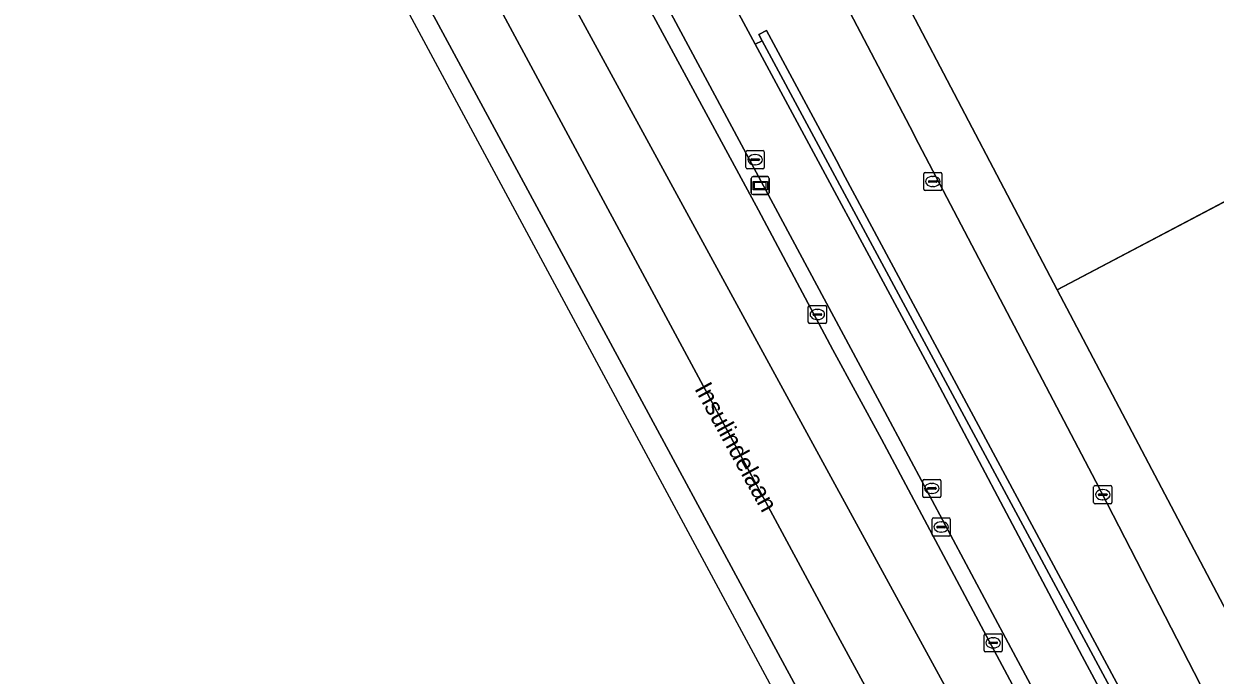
# Model space of a CAD drawing. Extents: x 162879 to 165540, y 384011 to 385181.
# Drawn here: x 162913.3 to 162979.1, y 384082.2 to 384118.2 of the extents above; entities that cross this region are included whole.
import ezdxf

# ---------------------------------------------------------------- set-up
doc = ezdxf.new("R2010")
doc.units = 0
for name, color, linetype in [('IMGEO_Berm_groen', 7, 'Continuous'), ('IMGEO_Berm_open', 7, 'Continuous'), ('IMGEO_Erf', 7, 'Continuous'), ('IMGEO_Fietspad_open', 7, 'Continuous'), ('IMGEO_Groenvoorziening', 7, 'Continuous'), ('IMGEO_Hek', 7, 'Continuous'), ('IMGEO_Kolk', 7, 'Continuous'), ('IMGEO_Muur', 7, 'Continuous'), ('IMGEO_Openbare_ruimte_label', 7, 'Continuous'), ('IMGEO_Rijbaan_regionaal_gesloten', 7, 'Continuous'), ('IMGEO_Rioolput', 7, 'Continuous'), ('IMGEO_Voetpad_open', 7, 'Continuous'), ('IMGEO_Wegwijzer', 7, 'Continuous')]:
    doc.layers.add(name, color=color, linetype=linetype)

msp = doc.modelspace()

# ---------------------------------------------------------------- linework, layer by layer
at = {"layer": 'IMGEO_Berm_groen'}
msp.add_lwpolyline([(162933.038, 384155.899), (162937.872, 384146.488), (162947.223, 384129.106), (162953.721, 384117.028), (162954.108, 384117.22), (162953.92, 384117.569), (162954.341, 384117.797), (162958.202, 384110.605), (162958.691, 384109.694), (162981.431, 384067.333), (162984.67, 384069.309), (162972.528, 384092.889), (162962.739, 384111.555), (162962.245, 384112.496), (162934.711, 384164.997)], dxfattribs=at)
at = {"layer": 'IMGEO_Berm_open'}
for points in [[(162930.309, 384154.083), (162929.465, 384153.664), (162929.808, 384152.971), (162933.346, 384146.147), (162936.921, 384139.438), (162942.396, 384129.219), (162947.989, 384118.779), (162953.892, 384107.862), (162957.998, 384100.168), (162960.687, 384095.222), (162966.347, 384084.631), (162969.056, 384079.527), (162972.201, 384073.655), (162975.924, 384066.775), (162977.549, 384063.861)], [(162978.275, 384064.218), (162977.652, 384065.394), (162972.657, 384074.738), (162967.836, 384083.704), (162960.872, 384096.737), (162947.738, 384121.235), (162934.999, 384144.935), (162933.549, 384147.714), (162932.265, 384150.139), (162930.309, 384154.083)]]:
    msp.add_lwpolyline(points, dxfattribs=at)
at = {"layer": 'IMGEO_Erf'}
msp.add_lwpolyline([(163003.813, 384097.747), (163004.613, 384098.171), (162997.371, 384111.834), (162989.485, 384113.534), (162970.391, 384103.478), (162987.483, 384071.025), (162995.091, 384074.97), (163000, 384077.515), (163012.207, 384083.845), (163007.504, 384092.716), (163006.694, 384092.288), (163005.778, 384094.016), (163003.752, 384092.942), (163002.029, 384096.192), (163004.066, 384097.271)], close=True, dxfattribs=at)
at = {"layer": 'IMGEO_Fietspad_open'}
for points in [[(162953.721, 384117.028), (162947.223, 384129.106), (162937.872, 384146.488), (162933.038, 384155.899)], [(162930.309, 384154.083), (162932.265, 384150.139), (162933.549, 384147.714), (162934.999, 384144.935), (162947.738, 384121.235), (162960.872, 384096.737), (162967.836, 384083.704), (162972.657, 384074.738), (162977.652, 384065.394), (162978.275, 384064.218)], [(162980.802, 384066.421), (162971.761, 384083.25), (162963.737, 384098.409), (162953.721, 384117.028)]]:
    msp.add_lwpolyline(points, dxfattribs=at)
at = {"layer": 'IMGEO_Groenvoorziening'}
msp.add_lwpolyline([(162962.154, 384119.148), (162970.391, 384103.478), (162989.485, 384113.534), (162997.371, 384111.834), (163004.613, 384098.171), (163007.401, 384092.911), (163010.958, 384094.796), (163011.072, 384094.58), (163015.763, 384085.73), (163017.147, 384083.12), (163017.364, 384083.229), (163017.549, 384082.865), (163022.409, 384085.444), (163024.815, 384086.721), (163049.609, 384099.879)], dxfattribs=at)
at = {"layer": 'IMGEO_Hek'}
msp.add_lwpolyline([(162970.391, 384103.478), (162987.968, 384112.735)], dxfattribs=at)
at = {"layer": 'IMGEO_Kolk'}
for p, q in [((162953.285, 384111.158), (162954.137, 384111.158)), ((162953.21, 384110.232), (162953.21, 384111.084)), ((162953.469, 384110.652), (162953.469, 384110.664)), ((162953.907, 384110.615), (162953.509, 384110.615)), ((162953.512, 384110.701), (162953.91, 384110.701)), ((162953.698, 384110.938), (162953.723, 384110.938)), ((162953.953, 384110.664), (162953.953, 384110.652)), ((162954.211, 384111.084), (162954.211, 384110.232)), ((162954.137, 384110.158), (162953.285, 384110.158)), ((162953.721, 384110.378), (162953.696, 384110.378)), ((162956.722, 384102.614), (162957.574, 384102.614)), ((162956.647, 384101.688), (162956.647, 384102.54)), ((162956.906, 384102.108), (162956.906, 384102.12)), ((162957.344, 384102.071), (162956.946, 384102.071)), ((162956.949, 384102.157), (162957.347, 384102.157)), ((162957.135, 384102.394), (162957.16, 384102.394)), ((162957.39, 384102.12), (162957.39, 384102.108)), ((162957.648, 384102.54), (162957.648, 384101.688)), ((162957.574, 384101.614), (162956.722, 384101.614)), ((162957.158, 384101.834), (162957.133, 384101.834)), ((162962.967, 384092.085), (162962.967, 384092.937)), ((162963.042, 384093.011), (162963.894, 384093.011)), ((162963.455, 384092.791), (162963.48, 384092.791)), ((162963.968, 384092.937), (162963.968, 384092.085)), ((162963.226, 384092.505), (162963.226, 384092.517)), ((162963.664, 384092.468), (162963.266, 384092.468)), ((162963.269, 384092.554), (162963.667, 384092.554)), ((162963.478, 384092.231), (162963.453, 384092.231)), ((162963.71, 384092.517), (162963.71, 384092.505)), ((162972.401, 384091.738), (162972.401, 384092.59)), ((162972.476, 384092.664), (162973.328, 384092.664)), ((162972.66, 384092.158), (162972.66, 384092.17)), ((162973.098, 384092.121), (162972.7, 384092.121)), ((162972.703, 384092.207), (162973.101, 384092.207)), ((162972.889, 384092.444), (162972.914, 384092.444)), ((162973.144, 384092.17), (162973.144, 384092.158)), ((162973.402, 384092.59), (162973.402, 384091.738)), ((162963.894, 384092.011), (162963.042, 384092.011)), ((162973.328, 384091.664), (162972.476, 384091.664)), ((162972.912, 384091.884), (162972.887, 384091.884)), ((162966.354, 384083.558), (162966.354, 384084.41)), ((162966.429, 384084.484), (162967.281, 384084.484)), ((162966.842, 384084.264), (162966.867, 384084.264)), ((162967.355, 384084.41), (162967.355, 384083.558)), ((162967.281, 384083.484), (162966.429, 384083.484)), ((162966.613, 384083.978), (162966.613, 384083.99)), ((162967.051, 384083.941), (162966.653, 384083.941)), ((162966.656, 384084.027), (162967.054, 384084.027)), ((162966.865, 384083.704), (162966.84, 384083.704)), ((162967.097, 384083.99), (162967.097, 384083.978))]:
    msp.add_line(p, q, dxfattribs=at)
for points in [[(162953.285, 384111.158), (162954.137, 384111.158)], [(162953.21, 384110.232), (162953.21, 384111.084)], [(162954.211, 384111.084), (162954.211, 384110.232)], [(162954.137, 384110.158), (162953.285, 384110.158)], [(162956.722, 384102.614), (162957.574, 384102.614)], [(162956.647, 384101.688), (162956.647, 384102.54)], [(162957.648, 384102.54), (162957.648, 384101.688)], [(162957.574, 384101.614), (162956.722, 384101.614)], [(162962.967, 384092.085), (162962.967, 384092.937)], [(162963.042, 384093.011), (162963.894, 384093.011)], [(162963.968, 384092.937), (162963.968, 384092.085)], [(162972.401, 384091.738), (162972.401, 384092.59)], [(162972.476, 384092.664), (162973.328, 384092.664)], [(162973.402, 384092.59), (162973.402, 384091.738)], [(162963.894, 384092.011), (162963.042, 384092.011)], [(162973.328, 384091.664), (162972.476, 384091.664)], [(162966.354, 384083.558), (162966.354, 384084.41)], [(162966.429, 384084.484), (162967.281, 384084.484)], [(162967.355, 384084.41), (162967.355, 384083.558)], [(162967.281, 384083.484), (162966.429, 384083.484)]]:
    msp.add_lwpolyline(points, dxfattribs=at)
for centre, radius, start, end in [((162953.287, 384111.082), 0.0765, 91.55205, 178.44795), ((162953.287, 384111.082), 0.0765, 91.55205, 178.44795), ((162954.135, 384111.082), 0.0765, 1.55205, 88.44795), ((162954.135, 384111.082), 0.0765, 1.55205, 88.44795), ((162953.509, 384110.661), 0.0403, 85.87752, 175.75265), ((162953.506, 384110.651), 0.0366, 178.93798, 274.71019), ((162953.91, 384110.658), 0.043, 264.86636, 352.45326), ((162953.914, 384110.663), 0.0386, 1.73085, 96.63898), ((162953.287, 384110.234), 0.0765, 181.55205, 268.44795), ((162953.287, 384110.234), 0.0765, 181.55205, 268.44795), ((162954.135, 384110.234), 0.0765, 271.55205, 358.44795), ((162954.135, 384110.234), 0.0765, 271.55205, 358.44795), ((162956.724, 384102.538), 0.0765, 91.55205, 178.44795), ((162956.724, 384102.538), 0.0765, 91.55205, 178.44795), ((162957.572, 384102.538), 0.0765, 1.55205, 88.44795), ((162957.572, 384102.538), 0.0765, 1.55205, 88.44795), ((162956.946, 384102.117), 0.0403, 85.87752, 175.75265), ((162956.943, 384102.107), 0.0366, 178.93798, 274.71019), ((162957.347, 384102.114), 0.043, 264.86636, 352.45326), ((162957.351, 384102.119), 0.0386, 1.73085, 96.63898), ((162956.724, 384101.69), 0.0765, 181.55205, 268.44795), ((162956.724, 384101.69), 0.0765, 181.55205, 268.44795), ((162957.572, 384101.69), 0.0765, 271.55205, 358.44795), ((162957.572, 384101.69), 0.0765, 271.55205, 358.44795), ((162963.044, 384092.935), 0.0765, 91.55205, 178.44795), ((162963.044, 384092.935), 0.0765, 91.55205, 178.44795), ((162963.892, 384092.935), 0.0765, 1.55205, 88.44795), ((162963.892, 384092.935), 0.0765, 1.55205, 88.44795), ((162963.044, 384092.087), 0.0765, 181.55205, 268.44795), ((162963.044, 384092.087), 0.0765, 181.55205, 268.44795), ((162963.266, 384092.514), 0.0403, 85.87752, 175.75265), ((162963.263, 384092.504), 0.0366, 178.93798, 274.71019), ((162963.667, 384092.511), 0.043, 264.86636, 352.45326), ((162963.671, 384092.516), 0.0386, 1.73085, 96.63898), ((162963.892, 384092.087), 0.0765, 271.55205, 358.44795), ((162963.892, 384092.087), 0.0765, 271.55205, 358.44795), ((162972.478, 384092.588), 0.0765, 91.55205, 178.44795), ((162972.478, 384092.588), 0.0765, 91.55205, 178.44795), ((162972.7, 384092.167), 0.0403, 85.87752, 175.75265), ((162972.697, 384092.157), 0.0366, 178.93798, 274.71019), ((162973.101, 384092.164), 0.043, 264.86636, 352.45326), ((162973.105, 384092.169), 0.0386, 1.73085, 96.63898), ((162973.326, 384092.588), 0.0765, 1.55205, 88.44795), ((162973.326, 384092.588), 0.0765, 1.55205, 88.44795), ((162972.478, 384091.74), 0.0765, 181.55205, 268.44795), ((162972.478, 384091.74), 0.0765, 181.55205, 268.44795), ((162973.326, 384091.74), 0.0765, 271.55205, 358.44795), ((162973.326, 384091.74), 0.0765, 271.55205, 358.44795), ((162966.431, 384084.408), 0.0765, 91.55205, 178.44795), ((162966.431, 384084.408), 0.0765, 91.55205, 178.44795), ((162967.279, 384084.408), 0.0765, 1.55205, 88.44795), ((162967.279, 384084.408), 0.0765, 1.55205, 88.44795), ((162966.431, 384083.56), 0.0765, 181.55205, 268.44795), ((162966.431, 384083.56), 0.0765, 181.55205, 268.44795), ((162966.653, 384083.987), 0.0403, 85.87752, 175.75265), ((162966.65, 384083.977), 0.0366, 178.93798, 274.71019), ((162967.054, 384083.984), 0.043, 264.86636, 352.45326), ((162967.058, 384083.989), 0.0386, 1.73085, 96.63898), ((162967.279, 384083.56), 0.0765, 271.55205, 358.44795), ((162967.279, 384083.56), 0.0765, 271.55205, 358.44795)]:
    msp.add_arc(centre, radius, start, end, dxfattribs=at)
for centre, major_axis, ratio, start_param, end_param in [((162953.697, 384110.658), (-0.387, 0.002), 0.722429, 4.712389, 7.853982), ((162953.722, 384110.658), (-0.39, 0.002), 0.717154, 1.570796, 4.712389), ((162957.134, 384102.114), (-0.387, 0.002), 0.722429, 4.712389, 7.853982), ((162957.159, 384102.114), (-0.39, 0.002), 0.717154, 1.570796, 4.712389), ((162963.454, 384092.511), (-0.387, 0.002), 0.722429, 4.712389, 7.853982), ((162963.479, 384092.511), (-0.39, 0.002), 0.717154, 1.570796, 4.712389), ((162972.888, 384092.164), (-0.387, 0.002), 0.722429, 4.712389, 7.853982), ((162972.913, 384092.164), (-0.39, 0.002), 0.717154, 1.570796, 4.712389), ((162966.841, 384083.984), (-0.387, 0.002), 0.722429, 4.712389, 7.853982), ((162966.866, 384083.984), (-0.39, 0.002), 0.717154, 1.570796, 4.712389)]:
    msp.add_ellipse(centre, major_axis=major_axis, ratio=ratio, start_param=start_param, end_param=end_param, dxfattribs=at)
at = {"layer": 'IMGEO_Muur'}
msp.add_lwpolyline([(162954.341, 384117.797), (162953.92, 384117.569), (162954.108, 384117.22), (162990.798, 384049.049), (162991.582, 384049.441), (163000.702, 384054.002), (163002.277, 384054.79), (163002.133, 384055.152), (163000.563, 384054.317), (162991.01, 384049.488), (162981.431, 384067.333), (162958.691, 384109.694), (162958.202, 384110.605)], close=True, dxfattribs=at)
at = {"layer": 'IMGEO_Rijbaan_regionaal_gesloten'}
for points in [[(162973.315, 384058.937), (162975.292, 384061.236), (162941.468, 384123.295), (162927.054, 384149.995), (162925.32, 384153.606), (162923.876, 384157.224), (162922.622, 384160.668), (162921.527, 384164.257), (162920.544, 384168.175), (162919.842, 384172.079), (162919.29, 384176.002), (162918.834, 384180.023), (162918.728, 384184.033), (162918.781, 384187.947), (162919.067, 384191.957), (162919.5, 384195.956)], [(162972.6, 384059.067), (162968.149, 384066.24), (162958.401, 384084.137), (162938.264, 384121.566), (162923.818, 384148.334), (162921.12, 384153.691), (162919.483, 384157.241), (162917.376, 384162.869), (162917.1, 384164.017), (162916.031, 384170.737)], [(162916.031, 384170.737), (162917.1, 384164.017), (162917.376, 384162.869), (162919.483, 384157.241), (162921.12, 384153.691), (162923.818, 384148.334), (162938.264, 384121.566), (162958.401, 384084.137), (162968.149, 384066.24), (162972.6, 384059.067)], [(162913.346, 384158.234), (162988.206, 384019.169)], [(162953.892, 384107.862), (162947.989, 384118.779), (162942.396, 384129.219), (162936.921, 384139.438), (162933.346, 384146.147), (162929.808, 384152.971), (162929.465, 384153.664)], [(162941.468, 384123.295), (162975.292, 384061.236), (162977.549, 384063.861), (162975.924, 384066.775), (162972.201, 384073.655), (162969.056, 384079.527), (162966.347, 384084.631), (162960.687, 384095.222), (162957.998, 384100.168), (162953.892, 384107.862)], [(162934.139, 384122.004), (162969.546, 384056.451), (162985.285, 384027.338), (162989.779, 384019.039), (162993.944, 384018.694), (162977.19, 384049.734), (162972.482, 384058.455)], [(162988.206, 384019.169), (162989.779, 384019.039), (162985.285, 384027.338), (162969.546, 384056.451), (162934.139, 384122.004)]]:
    msp.add_lwpolyline(points, dxfattribs=at)
at = {"layer": 'IMGEO_Rioolput'}
for p, q in [((162963.022, 384109.028), (162963.022, 384109.88)), ((162963.097, 384109.954), (162963.949, 384109.954)), ((162964.023, 384109.88), (162964.023, 384109.028)), ((162963.281, 384109.448), (162963.281, 384109.46)), ((162963.719, 384109.411), (162963.321, 384109.411)), ((162963.324, 384109.497), (162963.722, 384109.497)), ((162963.533, 384109.174), (162963.508, 384109.174)), ((162963.51, 384109.734), (162963.535, 384109.734)), ((162963.765, 384109.46), (162963.765, 384109.448)), ((162963.949, 384108.954), (162963.097, 384108.954)), ((162963.487, 384089.954), (162963.487, 384090.806)), ((162963.562, 384090.88), (162964.414, 384090.88)), ((162964.488, 384090.806), (162964.488, 384089.954)), ((162963.746, 384090.374), (162963.746, 384090.386)), ((162964.184, 384090.337), (162963.786, 384090.337)), ((162963.789, 384090.423), (162964.187, 384090.423)), ((162963.998, 384090.1), (162963.973, 384090.1)), ((162963.975, 384090.66), (162964, 384090.66)), ((162964.23, 384090.386), (162964.23, 384090.374)), ((162964.414, 384089.88), (162963.562, 384089.88))]:
    msp.add_line(p, q, dxfattribs=at)
for points in [[(162963.022, 384109.028), (162963.022, 384109.88)], [(162963.097, 384109.954), (162963.949, 384109.954)], [(162964.023, 384109.88), (162964.023, 384109.028)], [(162963.949, 384108.954), (162963.097, 384108.954)], [(162963.487, 384089.954), (162963.487, 384090.806)], [(162963.562, 384090.88), (162964.414, 384090.88)], [(162964.488, 384090.806), (162964.488, 384089.954)], [(162964.414, 384089.88), (162963.562, 384089.88)]]:
    msp.add_lwpolyline(points, dxfattribs=at)
for centre, radius, start, end in [((162963.099, 384109.878), 0.0765, 91.55205, 178.44795), ((162963.099, 384109.878), 0.0765, 91.55205, 178.44795), ((162963.947, 384109.878), 0.0765, 1.55205, 88.44795), ((162963.947, 384109.878), 0.0765, 1.55205, 88.44795), ((162963.321, 384109.457), 0.0403, 85.87752, 175.75265), ((162963.318, 384109.447), 0.0366, 178.93798, 274.71019), ((162963.722, 384109.454), 0.043, 264.86636, 352.45326), ((162963.726, 384109.459), 0.0386, 1.73085, 96.63898), ((162963.099, 384109.03), 0.0765, 181.55205, 268.44795), ((162963.099, 384109.03), 0.0765, 181.55205, 268.44795), ((162963.947, 384109.03), 0.0765, 271.55205, 358.44795), ((162963.947, 384109.03), 0.0765, 271.55205, 358.44795), ((162963.564, 384090.804), 0.0765, 91.55205, 178.44795), ((162963.564, 384090.804), 0.0765, 91.55205, 178.44795), ((162964.412, 384090.804), 0.0765, 1.55205, 88.44795), ((162964.412, 384090.804), 0.0765, 1.55205, 88.44795), ((162963.786, 384090.383), 0.0403, 85.87752, 175.75265), ((162963.783, 384090.373), 0.0366, 178.93798, 274.71019), ((162964.187, 384090.38), 0.043, 264.86636, 352.45326), ((162964.191, 384090.385), 0.0386, 1.73085, 96.63898), ((162963.564, 384089.956), 0.0765, 181.55205, 268.44795), ((162963.564, 384089.956), 0.0765, 181.55205, 268.44795), ((162964.412, 384089.956), 0.0765, 271.55205, 358.44795), ((162964.412, 384089.956), 0.0765, 271.55205, 358.44795)]:
    msp.add_arc(centre, radius, start, end, dxfattribs=at)
for centre, major_axis, ratio, start_param, end_param in [((162963.509, 384109.454), (-0.387, 0.002), 0.722429, 4.712389, 7.853982), ((162963.534, 384109.454), (-0.39, 0.002), 0.717154, 1.570796, 4.712389), ((162963.974, 384090.38), (-0.387, 0.002), 0.722429, 4.712389, 7.853982), ((162963.999, 384090.38), (-0.39, 0.002), 0.717154, 1.570796, 4.712389)]:
    msp.add_ellipse(centre, major_axis=major_axis, ratio=ratio, start_param=start_param, end_param=end_param, dxfattribs=at)
at = {"layer": 'IMGEO_Voetpad_open'}
for points in [[(162970.391, 384103.478), (162962.154, 384119.148), (162954.097, 384134.472), (162954.621, 384134.748), (162950.906, 384141.816), (162950.386, 384141.542), (162942.983, 384155.624), (162942.963, 384155.663), (162942.595, 384156.45), (162941.707, 384158.354), (162931.731, 384177.249), (162931.553, 384181.098), (162928.956, 384179.741)], [(162930.3, 384162.837), (162934.711, 384164.997), (162962.245, 384112.496), (162962.739, 384111.555), (162972.528, 384092.889), (162984.67, 384069.309), (162986.032, 384066.664), (162988.989, 384068.099), (162987.483, 384071.025), (162970.391, 384103.478)], [(162991.582, 384049.441), (162990.798, 384049.049), (162954.108, 384117.22), (162953.721, 384117.028), (162963.737, 384098.409), (162971.761, 384083.25), (162980.802, 384066.421)]]:
    msp.add_lwpolyline(points, dxfattribs=at)
at = {"layer": 'IMGEO_Wegwijzer'}
for p, q in [((162953.499, 384108.828), (162953.499, 384109.628)), ((162953.499, 384109.628), (162953.499, 384108.828)), ((162953.599, 384109.728), (162954.389, 384109.728)), ((162954.389, 384109.728), (162953.599, 384109.728)), ((162954.489, 384109.628), (162954.489, 384108.828)), ((162954.489, 384108.828), (162954.489, 384109.628)), ((162954.389, 384108.728), (162953.599, 384108.728)), ((162953.599, 384108.728), (162954.389, 384108.728))]:
    msp.add_line(p, q, dxfattribs=at)
for points in [[(162953.6, 384109.46), (162954.388, 384109.46), (162954.388, 384108.996), (162953.6, 384108.996), (162953.6, 384109.46)], [(162953.665, 384109.395), (162953.665, 384109.061), (162954.323, 384109.061), (162954.323, 384109.395), (162953.665, 384109.395)]]:
    msp.add_lwpolyline(points, dxfattribs=at)
for centre, start, end in [((162953.599, 384109.628), 90, 180), ((162953.599, 384109.628), 90, 180), ((162954.389, 384109.628), 0, 90), ((162954.389, 384109.628), 360, 90), ((162953.599, 384108.828), 180, 270), ((162953.599, 384108.828), 180, 270), ((162954.389, 384108.828), 270, 0), ((162954.389, 384108.828), 270, 0)]:
    msp.add_arc(centre, 0.1, start, end, dxfattribs=at)

# ---------------------------------------------------------------- texts
at = {"layer": 'IMGEO_Openbare_ruimte_label'}
msp.add_text('Insulindelaan', height=1, rotation=298.74304, dxfattribs=at).set_placement((162950.341, 384098.019))

doc.saveas('drawing.dxf')
